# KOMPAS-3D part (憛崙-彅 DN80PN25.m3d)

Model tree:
1. Объединить компоненты:1  (labels: СЕНС-ПФ DN80PN25)

Referenced files in D:\Савин\!СЕНСОР\3D для заказчика\!Новый перечень\СЕНС-ПФ\DN80\: СЕНС-ПФ DN80PN25.a3d
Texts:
  СЕНС-ПФ DN80PN25
  ООО НПП Сенсор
